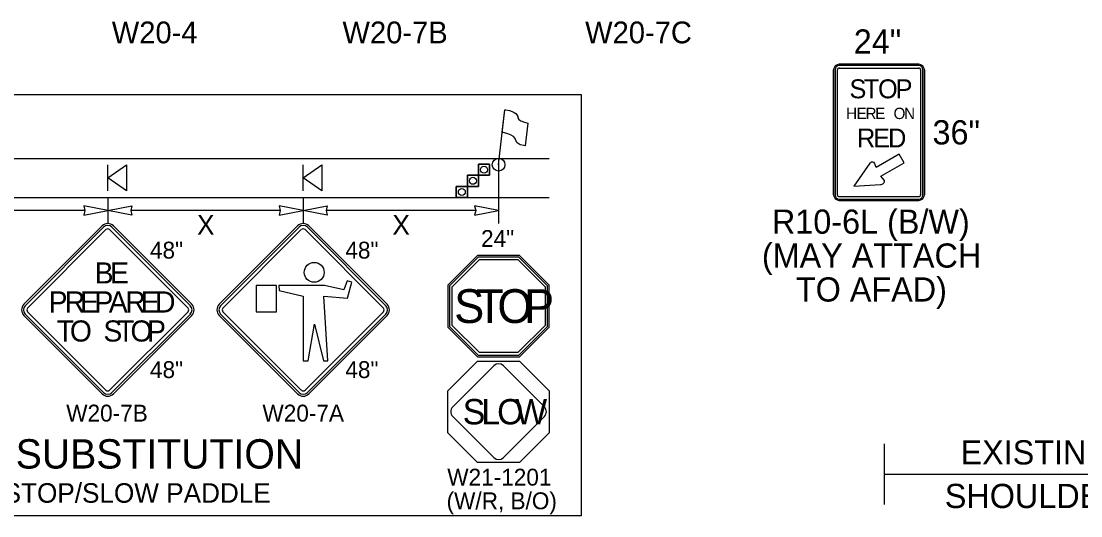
# Model space of a CAD drawing. Extents: x 99999.1 to 100095.7, y 99995 to 100010.7.
# Drawn here: x 100001.437 to 100004.94, y 100003.088 to 100004.722 of the extents above; entities that cross this region are included whole.
import ezdxf

# ---------------------------------------------------------------- set-up
doc = ezdxf.new("R2010")
doc.units = 0
for name, color, linetype in [('RD_ED_ShoulderPavedEdge', 7, 'Continuous'), ('RD_MK_LineEdgeWhite', 7, 'Continuous'), ('SH_DE_DetailHeading2Text', 7, 'Continuous'), ('TR_SN_ConstructionSigns', 7, 'Continuous'), ('TR_WZ_FlaggingStation', 7, 'Continuous'), ('TR_WZ_PortableSignMountBlk-Org', 7, 'Continuous'), ('TR_WZ_TrafficCone', 7, 'Continuous'), ('TR_WZ_WorkZoneDetails', 7, 'Continuous'), ('TR_WZ_WorkZoneTextCurrent', 7, 'Continuous')]:
    doc.layers.add(name, color=color, linetype=linetype)

msp = doc.modelspace()

# ---------------------------------------------------------------- linework, layer by layer
at = {"layer": 'RD_ED_ShoulderPavedEdge'}
msp.add_line((100000.2089, 100004.1394), (100003.1825, 100004.1394), dxfattribs=at)
at = {"layer": 'RD_MK_LineEdgeWhite'}
msp.add_line((100000.2089, 100004.2685), (100003.1825, 100004.2685), dxfattribs=at)
at = {"layer": 'TR_SN_ConstructionSigns'}
for p, q in [((100004.4041, 100004.5796), (100004.1416, 100004.5796)), ((100004.1416, 100004.5796), (100004.4041, 100004.5796)), ((100004.4041, 100004.5796), (100004.1416, 100004.5796)), ((100004.4041, 100004.5749), (100004.1416, 100004.5749)), ((100004.1229, 100004.5609), (100004.1229, 100004.1484)), ((100004.1229, 100004.1484), (100004.1229, 100004.5609)), ((100004.1229, 100004.5609), (100004.1229, 100004.1484)), ((100004.1276, 100004.5609), (100004.1276, 100004.1484)), ((100004.1354, 100004.1484), (100004.1354, 100004.5609)), ((100004.1416, 100004.5671), (100004.4041, 100004.5671)), ((100004.4104, 100004.5609), (100004.4104, 100004.1484)), ((100004.4182, 100004.1484), (100004.4182, 100004.5609)), ((100004.4229, 100004.1484), (100004.4229, 100004.5609)), ((100004.4229, 100004.5609), (100004.4229, 100004.1484)), ((100004.4229, 100004.1484), (100004.4229, 100004.5609)), ((100004.3396, 100004.2827), (100004.263, 100004.2385)), ((100004.356, 100004.2543), (100004.3396, 100004.2827)), ((100004.2424, 100004.2523), (100004.1898, 100004.1766)), ((100004.263, 100004.2385), (100004.2592, 100004.2511)), ((100004.2786, 100004.2096), (100004.356, 100004.2543)), ((100004.2909, 100004.1959), (100004.2786, 100004.2096)), ((100004.1898, 100004.1766), (100004.2776, 100004.1827)), ((100004.4041, 100004.1421), (100004.1416, 100004.1421)), ((100004.1416, 100004.1343), (100004.4041, 100004.1343)), ((100004.1416, 100004.1296), (100004.4041, 100004.1296)), ((100004.4041, 100004.1296), (100004.1416, 100004.1296)), ((100004.1416, 100004.1296), (100004.4041, 100004.1296)), ((100001.705, 100004.0456), (100001.4461, 100003.7866)), ((100002.001, 100003.7866), (100001.742, 100004.0456)), ((100002.351, 100004.0456), (100002.092, 100003.7866)), ((100002.6469, 100003.7866), (100002.388, 100004.0456)), ((100001.7097, 100004.0409), (100001.4507, 100003.782)), ((100001.4584, 100003.7743), (100001.7174, 100004.0332)), ((100001.7297, 100004.0332), (100001.9887, 100003.7743)), ((100001.9964, 100003.782), (100001.7374, 100004.0409)), ((100002.3556, 100004.0409), (100002.0966, 100003.782)), ((100002.1043, 100003.7743), (100002.3633, 100004.0332)), ((100002.3756, 100004.0332), (100002.6346, 100003.7743)), ((100002.6423, 100003.782), (100002.3833, 100004.0409)), ((100002.946, 100003.948), (100002.8479, 100003.8499)), ((100002.9482, 100003.9428), (100002.8531, 100003.8477)), ((100003.0847, 100003.948), (100002.946, 100003.948)), ((100003.0825, 100003.9428), (100002.9482, 100003.9428)), ((100003.1775, 100003.8477), (100003.0825, 100003.9428)), ((100003.1828, 100003.8499), (100003.0847, 100003.948)), ((100002.8619, 100003.8441), (100002.9518, 100003.934)), ((100002.9518, 100003.934), (100003.0789, 100003.934)), ((100003.0789, 100003.934), (100003.1688, 100003.8441)), ((100002.8479, 100003.8499), (100002.8479, 100003.7112)), ((100002.8531, 100003.8477), (100002.8531, 100003.7134)), ((100002.8619, 100003.717), (100002.8619, 100003.8441)), ((100003.1688, 100003.8441), (100003.1688, 100003.717)), ((100003.1775, 100003.7134), (100003.1775, 100003.8477)), ((100003.1828, 100003.7112), (100003.1828, 100003.8499)), ((100001.4461, 100003.7496), (100001.705, 100003.4906)), ((100001.4507, 100003.7542), (100001.7097, 100003.4952)), ((100001.7174, 100003.503), (100001.4584, 100003.7619)), ((100001.9887, 100003.7619), (100001.7297, 100003.503)), ((100001.7374, 100003.4952), (100001.9964, 100003.7542)), ((100001.742, 100003.4906), (100002.001, 100003.7496)), ((100002.092, 100003.7496), (100002.351, 100003.4906)), ((100002.0966, 100003.7542), (100002.3556, 100003.4952)), ((100002.3633, 100003.503), (100002.1043, 100003.7619)), ((100002.6346, 100003.7619), (100002.3756, 100003.503)), ((100002.3833, 100003.4952), (100002.6423, 100003.7542)), ((100002.388, 100003.4906), (100002.6469, 100003.7496)), ((100002.8479, 100003.7112), (100002.946, 100003.6131)), ((100002.8531, 100003.7134), (100002.9482, 100003.6184)), ((100002.9518, 100003.6271), (100002.8619, 100003.717)), ((100003.1688, 100003.717), (100003.0789, 100003.6271)), ((100003.0825, 100003.6184), (100003.1775, 100003.7134)), ((100003.0847, 100003.6131), (100003.1828, 100003.7112)), ((100003.0789, 100003.6271), (100002.9518, 100003.6271)), ((100002.946, 100003.6131), (100003.0847, 100003.6131)), ((100002.9482, 100003.6184), (100003.0825, 100003.6184)), ((100002.9996, 100003.5834), (100002.8637, 100003.4475)), ((100003.167, 100003.4475), (100003.0311, 100003.5834)), ((100002.8637, 100003.416), (100002.9996, 100003.2801)), ((100003.0311, 100003.2801), (100003.167, 100003.416))]:
    msp.add_line(p, q, dxfattribs=at)
for points in [[(100002.2135, 100003.8488), (100002.2135, 100003.7618), (100002.2814, 100003.7618), (100002.2814, 100003.8488)], [(100002.2894, 100003.849), (100002.2904, 100003.8322), (100002.3699, 100003.8137), (100002.3699, 100003.5995), (100002.3854, 100003.5995), (100002.4072, 100003.7212), (100002.4363, 100003.5995), (100002.451, 100003.5995), (100002.4381, 100003.8136), (100002.5158, 100003.8073), (100002.5305, 100003.8593), (100002.5145, 100003.8638), (100002.5042, 100003.8341), (100002.44, 100003.849)], [(100003.1828, 100003.5011), (100003.1828, 100003.3624), (100003.0847, 100003.2643), (100002.946, 100003.2643), (100002.8479, 100003.3624), (100002.8479, 100003.5011), (100002.946, 100003.5992), (100003.0847, 100003.5992)]]:
    msp.add_lwpolyline(points, close=True, dxfattribs=at)
msp.add_circle((100002.4059, 100003.8921), 0.0329, dxfattribs=at)
for centre, radius, start, end in [((100004.1416, 100004.5609), 0.0187, 90, 180), ((100004.1416, 100004.5609), 0.0187, 90, 180), ((100004.1416, 100004.5609), 0.0187, 90, 180), ((100004.1416, 100004.5609), 0.0141, 90, 180), ((100004.4041, 100004.5609), 0.0187, 0, 90), ((100004.4041, 100004.5609), 0.0187, 0, 90), ((100004.4041, 100004.5609), 0.0187, 0, 90), ((100004.4041, 100004.5609), 0.0141, 0, 90), ((100004.1416, 100004.5609), 0.00625, 90, 180), ((100004.4041, 100004.5609), 0.00625, 0, 90), ((100004.1416, 100004.1484), 0.0187, 180, 270), ((100004.1416, 100004.1484), 0.0187, 180, 270), ((100004.1416, 100004.1484), 0.0187, 180, 270), ((100004.1416, 100004.1484), 0.0141, 180, 270), ((100004.1416, 100004.1484), 0.00625, 180, 270), ((100004.4041, 100004.1484), 0.0187, 270, 0), ((100004.4041, 100004.1484), 0.0187, 270, 0), ((100004.4041, 100004.1484), 0.0187, 270, 0), ((100004.4041, 100004.1484), 0.0141, 270, 0), ((100004.4041, 100004.1484), 0.00625, 270, 0), ((100001.7235, 100004.0271), 0.0262, 45, 135), ((100001.7235, 100004.0271), 0.0196, 45, 135), ((100002.3695, 100004.0271), 0.0262, 45, 135), ((100002.3695, 100004.0271), 0.0196, 45, 135), ((100001.7235, 100004.0271), 0.00872, 45, 135), ((100002.3695, 100004.0271), 0.00872, 45, 135), ((100001.4646, 100003.7681), 0.0262, 135, 225), ((100001.4646, 100003.7681), 0.0196, 135, 225), ((100001.4646, 100003.7681), 0.00872, 135, 225), ((100001.9825, 100003.7681), 0.00872, 315, 45), ((100001.9825, 100003.7681), 0.0196, 315, 45), ((100001.9825, 100003.7681), 0.0262, 315, 45), ((100002.1105, 100003.7681), 0.0262, 135, 225), ((100002.1105, 100003.7681), 0.0196, 135, 225), ((100002.1105, 100003.7681), 0.00872, 135, 225), ((100002.6284, 100003.7681), 0.00872, 315, 45), ((100002.6284, 100003.7681), 0.0196, 315, 45), ((100002.6284, 100003.7681), 0.0262, 315, 45), ((100003.0153, 100003.5676), 0.0223, 45, 135), ((100001.7235, 100003.5091), 0.0262, 225, 315), ((100001.7235, 100003.5091), 0.0196, 225, 315), ((100001.7235, 100003.5091), 0.00872, 225, 315), ((100002.3695, 100003.5091), 0.0262, 225, 315), ((100002.3695, 100003.5091), 0.0196, 225, 315), ((100002.3695, 100003.5091), 0.00872, 225, 315), ((100002.8795, 100003.4318), 0.0223, 135, 225), ((100003.1512, 100003.4318), 0.0223, 315, 45), ((100003.0153, 100003.2959), 0.0223, 225, 315)]:
    msp.add_arc(centre, radius, start, end, dxfattribs=at)
for centre, major_axis, start_param, end_param in [((100004.2492, 100004.248), (0.00934, 0.00539), 5.977036, 8.198856), ((100004.2816, 100004.1909), (-0.00913, -0.00527), 0.771965, 3.092601)]:
    msp.add_ellipse(centre, major_axis=major_axis, ratio=0.700347, start_param=start_param, end_param=end_param, dxfattribs=at)
at = {"layer": 'TR_WZ_FlaggingStation'}
for p, q in [((100003.0154, 100004.2475), (100003.0361, 100004.429)), ((100003.0277, 100004.3554), (100003.0361, 100004.4292)), ((100003.1123, 100004.3854), (100003.1037, 100004.3097)), ((100003.0277, 100004.3554), (100003.0277, 100004.3554))]:
    msp.add_line(p, q, dxfattribs=at)
for points in [[(100003.0361, 100004.4292), (100003.0398, 100004.4284), (100003.0514, 100004.4262), (100003.0603, 100004.4235), (100003.0665, 100004.4196), (100003.0721, 100004.4165), (100003.0757, 100004.4121), (100003.0785, 100004.407), (100003.0788, 100004.403), (100003.0823, 100004.3971), (100003.0892, 100004.3923), (100003.0973, 100004.3889), (100003.1123, 100004.3854)], [(100003.1037, 100004.3097), (100003.0985, 100004.3106), (100003.087, 100004.3136), (100003.0769, 100004.3204), (100003.0727, 100004.3272), (100003.0702, 100004.3339), (100003.0643, 100004.3409), (100003.0572, 100004.345), (100003.046, 100004.3495), (100003.0277, 100004.3554)]]:
    msp.add_lwpolyline(points, dxfattribs=at)
msp.add_circle((100003.0154, 100004.2475), 0.021, dxfattribs=at)
at = {"layer": 'TR_WZ_PortableSignMountBlk-Org'}
for p, q in [((100001.7235, 100004.1609), (100001.7235, 100004.247)), ((100002.3695, 100004.1609), (100002.3695, 100004.247))]:
    msp.add_line(p, q, dxfattribs=at)
for points in [[(100001.7235, 100004.2039), (100001.7854, 100004.247), (100001.7854, 100004.1609)], [(100002.3695, 100004.2039), (100002.4313, 100004.247), (100002.4313, 100004.1609)]]:
    msp.add_lwpolyline(points, close=True, dxfattribs=at)
at = {"layer": 'TR_WZ_TrafficCone'}
for points in [[(100002.9491, 100004.2496), (100002.9858, 100004.2496), (100002.9858, 100004.2128), (100002.9491, 100004.2128), (100002.9491, 100004.2496)], [(100002.9491, 100004.2128), (100002.9858, 100004.2128), (100002.9858, 100004.2496), (100002.9491, 100004.2496), (100002.9491, 100004.2128)], [(100002.9123, 100004.2128), (100002.9491, 100004.2128), (100002.9491, 100004.1761), (100002.9123, 100004.1761), (100002.9123, 100004.2128)], [(100002.9123, 100004.1761), (100002.9491, 100004.1761), (100002.9491, 100004.2128), (100002.9123, 100004.2128), (100002.9123, 100004.1761)], [(100002.8756, 100004.1761), (100002.9123, 100004.1761), (100002.9123, 100004.1394), (100002.8756, 100004.1394), (100002.8756, 100004.1761)], [(100002.8756, 100004.1394), (100002.9123, 100004.1394), (100002.9123, 100004.1761), (100002.8756, 100004.1761), (100002.8756, 100004.1394)]]:
    msp.add_lwpolyline(points, dxfattribs=at)
for centre in [(100002.9674, 100004.2312), (100002.9307, 100004.1945), (100002.8939, 100004.1577)]:
    msp.add_circle(centre, 0.0115, dxfattribs=at)
at = {"layer": 'TR_WZ_WorkZoneDetails'}
for p, q in [((100003.0154, 100004.2685), (100003.0154, 100004.0532)), ((100001.7235, 100004.1394), (100001.7235, 100004.0532)), ((100002.3695, 100004.1394), (100002.3695, 100004.0532)), ((100001.6479, 100004.0963), (100001.1533, 100004.0963)), ((100002.2938, 100004.0963), (100001.7992, 100004.0963)), ((100002.9397, 100004.0963), (100002.4452, 100004.0963)), ((100004.2907, 100003.1255), (100004.2907, 100003.3255)), ((100004.2907, 100003.2255), (100005.2907, 100003.2255))]:
    msp.add_line(p, q, dxfattribs=at)
for points in [[(100001.7235, 100004.0963), (100001.6442, 100004.1119), (100001.6479, 100004.0963), (100001.6442, 100004.0807)], [(100001.7235, 100004.0963), (100001.8029, 100004.1119), (100001.7992, 100004.0963), (100001.8029, 100004.0807)], [(100002.3695, 100004.0963), (100002.2901, 100004.1119), (100002.2938, 100004.0963), (100002.2901, 100004.0807)], [(100002.3695, 100004.0963), (100002.4488, 100004.1119), (100002.4452, 100004.0963), (100002.4488, 100004.0807)], [(100003.0154, 100004.0963), (100002.9361, 100004.1119), (100002.9397, 100004.0963), (100002.9361, 100004.0807)]]:
    msp.add_lwpolyline(points, close=True, dxfattribs=at)
at = {"layer": 'TR_WZ_WorkZoneTextCurrent'}
msp.add_lwpolyline([(100000.1, 100004.4792), (100003.2886, 100004.4792), (100003.2886, 100003.0879), (100000.1, 100003.0879)], close=True, dxfattribs=at)

# ---------------------------------------------------------------- texts
at = {"layer": 'SH_DE_DetailHeading2Text'}
msp.add_text('HUMAN FLAGGER SUBSTITUTION', height=0.09689, rotation=360, dxfattribs=at).set_placement((100000.2529, 100003.244))
at = {"layer": 'TR_SN_ConstructionSigns'}
for s, height, p in [('W20-4', 0.072, (100001.7367, 100004.6486)), ('W20-7B', 0.072, (100002.4993, 100004.6486)), ('W20-7C', 0.072, (100003.3014, 100004.6486)), ('24"', 0.08, (100004.1895, 100004.6146)), ('36"', 0.08, (100004.4498, 100004.3146)), ('R10-6L (B/W)', 0.08, (100003.919, 100004.0196)), ('48"', 0.05581, (100001.8629, 100003.9375)), ('48"', 0.05581, (100002.5088, 100003.9375)), ('(MAY ATTACH', 0.08, (100003.8858, 100003.9076)), ('TO AFAD)', 0.08, (100003.9982, 100003.7956)), ('48"', 0.05581, (100001.8629, 100003.5429)), ('48"', 0.05581, (100002.5088, 100003.5429)), ('W20-7B', 0.05581, (100001.5861, 100003.3992)), ('W20-7A', 0.05581, (100002.2347, 100003.3992)), ('W21-1201', 0.05581, (100002.8457, 100003.1876)), ('(W/R, B/O)', 0.05581, (100002.8434, 100003.1095))]:
    msp.add_text(s, height=height, rotation=360, dxfattribs=at).set_placement(p)
for s, height, p in [('S', 0.0625, (100004.1754, 100004.4671)), ('T', 0.0625, (100004.2229, 100004.4671)), ('O', 0.0625, (100004.2698, 100004.4671)), ('P', 0.0625, (100004.3279, 100004.4671)), ('H', 0.0375, (100004.1643, 100004.3984)), ('E', 0.0375, (100004.1988, 100004.3984)), ('R', 0.0375, (100004.2284, 100004.3984)), ('E', 0.0375, (100004.2603, 100004.3984)), ('O', 0.0375, (100004.3211, 100004.3984)), ('N', 0.0375, (100004.3559, 100004.3984)), ('R', 0.0625, (100004.2004, 100004.3046)), ('E', 0.0625, (100004.2535, 100004.3046)), ('D', 0.0625, (100004.3029, 100004.3046)), ('24"', 0.05581, (100002.9574, 100003.9759)), ('B', 0.0698, (100001.6803, 100003.8553)), ('E', 0.0698, (100001.7312, 100003.8553)), ('S', 0.1116, (100002.8686, 100003.7248)), ('T', 0.1116, (100002.9411, 100003.7248)), ('O', 0.1116, (100003.0114, 100003.7248)), ('P', 0.1116, (100003.0996, 100003.7248)), ('P', 0.0698, (100001.5282, 100003.7594)), ('R', 0.0698, (100001.5812, 100003.7594)), ('E', 0.0698, (100001.6321, 100003.7594)), ('P', 0.0698, (100001.6796, 100003.7594)), ('A', 0.0698, (100001.727, 100003.7594)), ('R', 0.0698, (100001.7814, 100003.7594)), ('E', 0.0698, (100001.8324, 100003.7594)), ('D', 0.0698, (100001.8798, 100003.7594)), ('T', 0.0698, (100001.5544, 100003.6635)), ('O', 0.0698, (100001.5983, 100003.6635)), ('S', 0.0698, (100001.7092, 100003.6635)), ('T', 0.0698, (100001.7546, 100003.6635)), ('O', 0.0698, (100001.7985, 100003.6635)), ('P', 0.0698, (100001.8536, 100003.6635)), ('S', 0.0837, (100002.8969, 100003.3899)), ('L', 0.0837, (100002.958, 100003.3899)), ('O', 0.0837, (100003.0107, 100003.3899)), ('W', 0.0837, (100003.0702, 100003.3899))]:
    msp.add_text(s, height=height, dxfattribs=at).set_placement(p)
at = {"layer": 'TR_WZ_WorkZoneDetails'}
for s, p in [('EXISTING', (100004.5424, 100003.2575)), ('SHOULDER', (100004.4905, 100003.1135))]:
    msp.add_text(s, height=0.08, rotation=360, dxfattribs=at).set_placement(p)
at = {"layer": 'TR_WZ_WorkZoneTextCurrent'}
for s, height, p in [('X', 0.0646, (100002.0185, 100004.0166)), ('X', 0.0646, (100002.6644, 100004.0166)), ('UPDATE SIGNAGE & USE STOP/SLOW PADDLE', 0.064593, (100000.304, 100003.131))]:
    msp.add_text(s, height=height, dxfattribs=at).set_placement(p)

doc.saveas('drawing.dxf')
